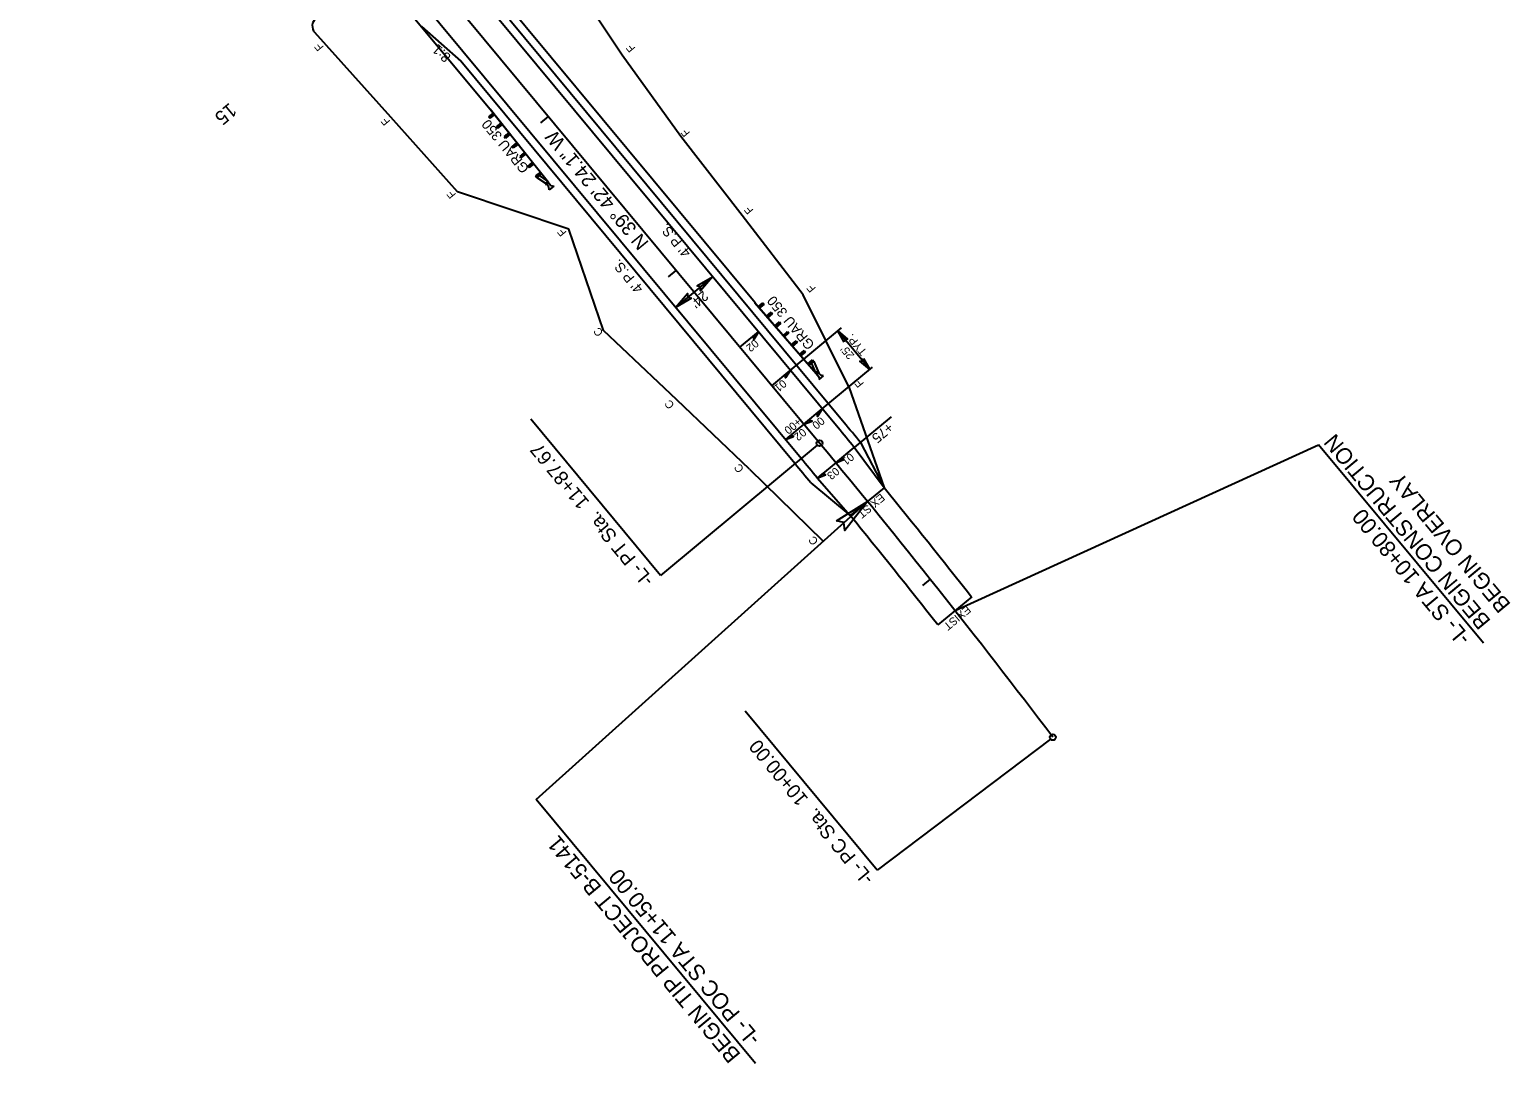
# Model space of a CAD drawing. Extents: x 2597570 to 2598622, y 852675 to 853890.
# Drawn here: x 2597882 to 2598622, y 852675 to 853192 of the extents above; entities that cross this region are included whole.
import ezdxf

# ---------------------------------------------------------------- set-up
doc = ezdxf.new("R2010")
doc.units = 0
for name, color, linetype in [('Exist Drainage Structure Bridge Pier Bent Interior', 7, 'Continuous'), ('Exist Hydrographic Channel Edge', 7, 'Continuous'), ('Exist Plan Preparation Drainage Arrows Symbol CELL', 7, 'Continuous'), ('Exist Plan Preparation Watershed Blue', 7, 'Continuous'), ('Exist Structure Major Deck Tunnel Box Culvert', 7, 'Continuous'), ('Prop Drainage Structure Box Number Symbol CELL', 7, 'Continuous'), ('Prop Drainage Structure Drop Inlet Grate 2 Narrow Slots and Flat Grates 840 29 Label', 7, 'Continuous'), ('Prop Drainage Structure Gutter Shoulder Berm Label', 7, 'Continuous'), ('Prop Drainage Structure Pipe Alternate 15in', 7, 'Continuous'), ('Prop Drainage Structure Pipe Alternate 15in Label', 7, 'Continuous'), ('Prop Drainage Structure Pipe RCP 15in Class IV', 7, 'Continuous'), ('Prop Drainage Structure Pipe RCP 15in Class IV Label', 7, 'Continuous'), ('Prop Drainage Structure Plot Symbol 20 Scale', 7, 'Continuous'), ('Prop Drainage Structure Plot Symbol 50 Scale', 7, 'Continuous'), ('Prop Earthen Structure Base Ditch Berm Detail Label', 7, 'Continuous'), ('Prop Earthen Structure Ditch Flow Line', 7, 'Continuous'), ('Prop Erosion Rip Rap Pad at Outlet CELL', 7, 'Continuous'), ('Prop Erosion Rip Rap Pad at Outlet Label', 7, 'Continuous'), ('Raster_Level_0', 7, 'Continuous'), ('Typical Terminator CELL', 7, 'Continuous')]:
    doc.layers.add(name, color=color, linetype=linetype)

msp = doc.modelspace()

# ---------------------------------------------------------------- linework, layer by layer
at = {"layer": 'Exist Drainage Structure Bridge Pier Bent Interior'}
for p, q in [((2598196.95, 852918.86), (2598132.12, 852996.93)), ((2598275.35, 852983.97), (2598196.95, 852918.86)), ((2598305.3, 852771.42), (2598239.24, 852850.98)), ((2598391.92, 852837), (2598305.3, 852771.42))]:
    msp.add_line(p, q, dxfattribs=at)
for centre in [(2598276.51, 852984.93), (2598393.11, 852837.9)]:
    msp.add_circle(centre, 1.5, dxfattribs=at)
at = {"layer": 'Exist Hydrographic Channel Edge'}
msp.add_line((2598276.51, 852984.93), (2597890.84, 853449.35), dxfattribs=at)
msp.add_line((2598276.51, 852984.93), (2597890.84, 853449.35), dxfattribs=at)
msp.add_arc((2595067.53, 850320.15), 4171.16, 37.12886, 39.70669, dxfattribs=at)
msp.add_arc((2595067.53, 850320.15), 4171.16, 37.12886, 39.70669, dxfattribs=at)
at = {"layer": 'Exist Plan Preparation Drainage Arrows Symbol CELL'}
for p, q in [((2598140.86, 853148.28), (2598137.01, 853145.09)), ((2598204.74, 853071.35), (2598200.9, 853068.16)), ((2598268.63, 852994.42), (2598264.78, 852991.22)), ((2598331.8, 852916.9), (2598327.89, 852913.79))]:
    msp.add_line(p, q, dxfattribs=at)
at = {"layer": 'Exist Plan Preparation Watershed Blue'}
for p, q in [((2598113.37, 853150), (2598111.02, 853148.13)), ((2598112.82, 853148.28), (2598111.02, 853148.13)), ((2598111.02, 853148.13), (2598111.65, 853147.35)), ((2598113.99, 853149.22), (2598111.65, 853147.35)), ((2598111.65, 853147.35), (2598112.2, 853149.06)), ((2598111.78, 853151.99), (2598140.93, 853115.43)), ((2598112.2, 853149.06), (2598113.99, 853149.22)), ((2598112.2, 853149.06), (2598112.82, 853148.28)), ((2598112.82, 853148.28), (2598113.37, 853150)), ((2598113.99, 853149.22), (2598112.82, 853148.28)), ((2598113.37, 853150), (2598113.99, 853149.22)), ((2598117.3, 853145.07), (2598114.91, 853143.17)), ((2598116.73, 853143.34), (2598114.91, 853143.17)), ((2598114.91, 853143.17), (2598115.53, 853142.39)), ((2598117.92, 853144.29), (2598115.53, 853142.39)), ((2598115.53, 853142.39), (2598116.1, 853144.12)), ((2598116.1, 853144.12), (2598117.92, 853144.29)), ((2598116.1, 853144.12), (2598116.73, 853143.34)), ((2598117.3, 853145.07), (2598116.73, 853143.34)), ((2598121.23, 853140.15), (2598118.84, 853138.25)), ((2598121.85, 853139.36), (2598119.47, 853137.46)), ((2598119.47, 853137.46), (2598120.03, 853139.2)), ((2598120.03, 853139.2), (2598121.85, 853139.36)), ((2598120.03, 853139.2), (2598120.66, 853138.41)), ((2598121.23, 853140.15), (2598120.66, 853138.41)), ((2598120.66, 853138.41), (2598118.84, 853138.25)), ((2598118.84, 853138.25), (2598119.47, 853137.46)), ((2598125.15, 853135.22), (2598122.78, 853133.33)), ((2598124.59, 853133.49), (2598122.78, 853133.33)), ((2598122.78, 853133.33), (2598123.4, 853132.54)), ((2598125.78, 853134.44), (2598123.4, 853132.54)), ((2598123.4, 853132.54), (2598123.97, 853134.27)), ((2598123.97, 853134.27), (2598125.78, 853134.44)), ((2598123.97, 853134.27), (2598124.59, 853133.49)), ((2598125.15, 853135.22), (2598124.59, 853133.49)), ((2598125.15, 853135.22), (2598125.78, 853134.44)), ((2598129.08, 853130.29), (2598126.63, 853128.34)), ((2598128.48, 853128.53), (2598126.63, 853128.34)), ((2598126.63, 853128.34), (2598127.25, 853127.55)), ((2598129.71, 853129.51), (2598127.25, 853127.55)), ((2598127.25, 853127.55), (2598127.86, 853129.32)), ((2598127.86, 853129.32), (2598129.71, 853129.51)), ((2598127.86, 853129.32), (2598128.48, 853128.53)), ((2598129.08, 853130.29), (2598128.48, 853128.53)), ((2598133.01, 853125.37), (2598130.67, 853123.5)), ((2598133.63, 853124.58), (2598131.29, 853122.71)), ((2598131.29, 853122.71), (2598131.84, 853124.43)), ((2598131.84, 853124.43), (2598133.63, 853124.58)), ((2598131.84, 853124.43), (2598132.46, 853123.65)), ((2598133.01, 853125.37), (2598132.46, 853123.65)), ((2598132.46, 853123.65), (2598130.67, 853123.5)), ((2598130.67, 853123.5), (2598131.29, 853122.71)), ((2598136.94, 853120.44), (2598134.54, 853118.53)), ((2598136.37, 853118.7), (2598134.54, 853118.53)), ((2598134.54, 853118.53), (2598135.17, 853117.75)), ((2598137.56, 853119.66), (2598135.17, 853117.75)), ((2598135.17, 853117.75), (2598135.74, 853119.48)), ((2598135.17, 853117.75), (2598139.45, 853114.89)), ((2598135.74, 853119.48), (2598137.56, 853119.66)), ((2598135.74, 853119.48), (2598136.37, 853118.7)), ((2598136.94, 853120.44), (2598136.37, 853118.7)), ((2598136.37, 853118.7), (2598140.62, 853115.82)), ((2598140.62, 853115.82), (2598139.45, 853114.89)), ((2598141.24, 853115.04), (2598139.45, 853114.89)), ((2598139.45, 853114.89), (2598139.76, 853114.5)), ((2598139.45, 853114.89), (2598140.07, 853114.11)), ((2598139.95, 853114.58), (2598140.42, 853114.97)), ((2598141.25, 853113.01), (2598139.95, 853114.58)), ((2598140.07, 853114.11), (2598140.62, 853115.82)), ((2598141.24, 853115.04), (2598140.07, 853114.11)), ((2598140.42, 853114.97), (2598140.89, 853115.36)), ((2598140.89, 853115.36), (2598142.2, 853113.78)), ((2598141.35, 853111.55), (2598141.25, 853113.01)), ((2598143.61, 853113.43), (2598141.35, 853111.55)), ((2598142.2, 853113.78), (2598143.61, 853113.43)), ((2598244.23, 853055.06), (2598274.81, 853019.7)), ((2598245.89, 853053.14), (2598248.16, 853055.1)), ((2598247.68, 853053.37), (2598245.89, 853053.14)), ((2598245.89, 853053.14), (2598246.55, 853052.39)), ((2598246.55, 853052.39), (2598248.82, 853054.35)), ((2598247.03, 853054.12), (2598246.55, 853052.39)), ((2598246.55, 853052.39), (2598247.68, 853053.37)), ((2598248.82, 853054.35), (2598247.03, 853054.12)), ((2598247.03, 853054.12), (2598247.68, 853053.37)), ((2598247.68, 853053.37), (2598248.16, 853055.1)), ((2598248.16, 853055.1), (2598248.82, 853054.35)), ((2598250.01, 853048.38), (2598252.32, 853050.37)), ((2598251.82, 853048.62), (2598252.32, 853050.37)), ((2598252.32, 853050.37), (2598252.98, 853049.62)), ((2598250.01, 853048.38), (2598251.82, 853048.62)), ((2598250.67, 853047.62), (2598252.98, 853049.62)), ((2598251.17, 853049.37), (2598250.67, 853047.62)), ((2598252.98, 853049.62), (2598251.17, 853049.37)), ((2598251.17, 853049.37), (2598251.82, 853048.62)), ((2598254.13, 853043.61), (2598256.44, 853045.6)), ((2598254.13, 853043.61), (2598255.94, 853043.85)), ((2598254.79, 853042.85), (2598257.09, 853044.85)), ((2598255.29, 853044.61), (2598254.79, 853042.85)), ((2598257.09, 853044.85), (2598255.29, 853044.61)), ((2598255.29, 853044.61), (2598255.94, 853043.85)), ((2598255.94, 853043.85), (2598256.44, 853045.6)), ((2598256.44, 853045.6), (2598257.09, 853044.85)), ((2598258.26, 853038.84), (2598260.55, 853040.83)), ((2598258.26, 853038.84), (2598260.06, 853039.08)), ((2598258.26, 853038.84), (2598258.91, 853038.09)), ((2598258.91, 853038.09), (2598261.21, 853040.07)), ((2598259.41, 853039.84), (2598258.91, 853038.09)), ((2598261.21, 853040.07), (2598259.41, 853039.84)), ((2598259.41, 853039.84), (2598260.06, 853039.08)), ((2598260.06, 853039.08), (2598260.55, 853040.83)), ((2598260.55, 853040.83), (2598261.21, 853040.07)), ((2598262.38, 853034.08), (2598264.75, 853036.13)), ((2598263.03, 853033.32), (2598265.41, 853035.37)), ((2598265.41, 853035.37), (2598263.56, 853035.1)), ((2598264.22, 853034.35), (2598264.75, 853036.13)), ((2598264.75, 853036.13), (2598265.41, 853035.37)), ((2598262.38, 853034.08), (2598264.22, 853034.35)), ((2598263.56, 853035.1), (2598263.03, 853033.32)), ((2598263.56, 853035.1), (2598264.22, 853034.35)), ((2598266.5, 853029.31), (2598268.77, 853031.27)), ((2598266.5, 853029.31), (2598268.29, 853029.53)), ((2598267.15, 853028.55), (2598269.42, 853030.51)), ((2598267.63, 853030.29), (2598267.15, 853028.55)), ((2598269.42, 853030.51), (2598267.63, 853030.29)), ((2598267.63, 853030.29), (2598268.29, 853029.53)), ((2598268.29, 853029.53), (2598268.77, 853031.27)), ((2598268.77, 853031.27), (2598269.42, 853030.51)), ((2598270.62, 853024.54), (2598272.94, 853026.55)), ((2598270.62, 853024.54), (2598272.43, 853024.79)), ((2598271.28, 853023.79), (2598273.59, 853025.79)), ((2598271.78, 853025.54), (2598271.28, 853023.79)), ((2598273.59, 853025.79), (2598271.78, 853025.54)), ((2598271.78, 853025.54), (2598272.43, 853024.79)), ((2598272.43, 853024.79), (2598272.94, 853026.55)), ((2598272.43, 853024.79), (2598274.48, 853020.08)), ((2598272.94, 853026.55), (2598273.59, 853025.79)), ((2598273.59, 853025.79), (2598275.62, 853021.06)), ((2598274.48, 853020.08), (2598275.62, 853021.06)), ((2598275.13, 853019.32), (2598275.62, 853021.06)), ((2598275.62, 853021.06), (2598275.94, 853020.68)), ((2598275.62, 853021.06), (2598276.27, 853020.3)), ((2598276.27, 853020.3), (2598274.48, 853020.08)), ((2598275.35, 853020.12), (2598274.89, 853019.73)), ((2598274.89, 853019.73), (2598276.2, 853018.15)), ((2598275.13, 853019.32), (2598276.27, 853020.3)), ((2598275.82, 853020.51), (2598275.35, 853020.12)), ((2598277.13, 853018.94), (2598275.82, 853020.51)), ((2598276.2, 853018.15), (2598276.29, 853016.7)), ((2598276.29, 853016.7), (2598278.55, 853018.58)), ((2598278.55, 853018.58), (2598277.13, 853018.94))]:
    msp.add_line(p, q, dxfattribs=at)
at = {"layer": 'Prop Drainage Structure Box Number Symbol CELL'}
for points in [[(2598215.08, 853063.59), (2598222.99, 853068.15), (2598217.05, 853061.14), (2598216.92, 853063.1)], [(2598212.44, 853057.37), (2598204.53, 853052.82), (2598210.47, 853059.83), (2598210.61, 853057.86)], [(2598288.82, 853035.49), (2598285.63, 853041.03), (2598290.54, 853036.87), (2598289.16, 853036.78)], [(2598298.41, 853027.34), (2598301.6, 853021.8), (2598296.69, 853025.96), (2598298.07, 853026.05)], [(2598284.99, 852946.1), (2598300.44, 852955.84), (2598289.13, 852941.35), (2598288.7, 852945.27)]]:
    msp.add_lwpolyline(points, close=True, dxfattribs=at)
at = {"layer": 'Prop Drainage Structure Drop Inlet Grate 2 Narrow Slots and Flat Grates 840 29 Label'}
for points in [[(2598245.92, 853040.55), (2598243.58, 853036.79), (2598243.42, 853038.48)], [(2598261.89, 853021.32), (2598259.55, 853017.56), (2598259.4, 853019.25)], [(2598277.86, 853002.08), (2598275.52, 852998.33), (2598275.37, 853000.02)], [(2598268.63, 852994.42), (2598272.75, 852996.03), (2598271.12, 852996.49)], [(2598259.4, 852986.75), (2598263.52, 852988.36), (2598261.89, 852988.82)], [(2598284.6, 852975.18), (2598288.72, 852976.79), (2598287.09, 852977.26)], [(2598275.35, 852967.51), (2598279.48, 852969.12), (2598277.84, 852969.58)]]:
    msp.add_lwpolyline(points, close=True, dxfattribs=at)
at = {"layer": 'Prop Drainage Structure Gutter Shoulder Berm Label'}
for p, q in [((2598223, 853068.15), (2598204.53, 853052.82)), ((2598312.3, 852998.18), (2598293.83, 852982.85))]:
    msp.add_line(p, q, dxfattribs=at)
at = {"layer": 'Prop Drainage Structure Pipe Alternate 15in'}
for p, q in [((2598168.51, 853041.26), (2598151.17, 853091.85)), ((2598291.22, 853013.18), (2598308.74, 852962.61)), ((2598241.49, 852971.88), (2598278.09, 852936.11))]:
    msp.add_line(p, q, dxfattribs=at)
at = {"layer": 'Prop Drainage Structure Pipe RCP 15in Class IV'}
for p, q in [((2598177.77, 853178.93), (2598150.05, 853220.91)), ((2598062.12, 853147.89), (2598024.19, 853190.17)), ((2598207.09, 853138.29), (2598177.77, 853178.93)), ((2598095.49, 853110.61), (2598062.12, 853147.89)), ((2598237.81, 853098.81), (2598207.09, 853138.29)), ((2598151.17, 853091.85), (2598095.49, 853110.61)), ((2598268.26, 853059.11), (2598237.81, 853098.81)), ((2598291.22, 853013.18), (2598268.26, 853059.11)), ((2598291.22, 853013.18), (2598291.22, 853013.18))]:
    msp.add_line(p, q, dxfattribs=at)
msp.add_arc((2598027.92, 853193.51), 5, 129.70669, 221.8952, dxfattribs=at)
at = {"layer": 'Prop Drainage Structure Pipe RCP 15in Class IV Label'}
for p, q in [((2598344.22, 852901.22), (2598525.93, 852984.16)), ((2598608.35, 852884.9), (2598525.93, 852984.16)), ((2598134.88, 852806.8), (2598300.44, 852955.84)), ((2598244.4, 852674.91), (2598134.88, 852806.8))]:
    msp.add_line(p, q, dxfattribs=at)
at = {"layer": 'Prop Drainage Structure Plot Symbol 20 Scale'}
for p, q in [((2598285.74, 852992.6), (2597900.08, 853457.02)), ((2598267.28, 852977.26), (2597881.61, 853441.69)), ((2598308.74, 852962.61), (2598293.82, 852982.84)), ((2598275.28, 852967.59), (2598291.8, 852948.8)), ((2598352.67, 852908.11), (2598335.58, 852894.18))]:
    msp.add_line(p, q, dxfattribs=at)
for centre, radius, start, end in [((2595076.76, 850327.82), 4171.16, 39.53269, 39.70669), ((2595067.53, 850320.15), 4159.16, 39.53368, 39.70669), ((2595067.53, 850320.15), 4181.87, 38.23022, 39.18929), ((2595067.53, 850320.15), 4160.01, 38.22518, 39.18929)]:
    msp.add_arc(centre, radius, start, end, dxfattribs=at)
at = {"layer": 'Prop Drainage Structure Plot Symbol 50 Scale'}
for p, q in [((2598077.56, 853193.2), (2598097.17, 853175.85)), ((2598288.82, 852995.15), (2598121.7, 853196.4)), ((2598264.2, 852974.71), (2598097.17, 853175.85)), ((2598296.97, 852985.3), (2598308.74, 852962.61)), ((2598272.2, 852965.04), (2598291.8, 852948.8)), ((2598291.8, 852948.8), (2598291.8, 852948.8))]:
    msp.add_line(p, q, dxfattribs=at)
for radius, start in [(4187.16, 39.53171), (4155.16, 39.53368)]:
    msp.add_arc((2595067.53, 850320.15), radius, start, 39.70669, dxfattribs=at)
at = {"layer": 'Prop Earthen Structure Ditch Flow Line'}
for p, q in [((2598236.69, 853032.88), (2598245.92, 853040.55)), ((2598261.89, 853021.32), (2598287.43, 853042.53)), ((2598301.6, 853021.8), (2598285.63, 853041.03)), ((2598252.66, 853013.65), (2598261.89, 853021.32)), ((2598277.86, 853002.08), (2598302.92, 853022.9)), ((2598268.63, 852994.42), (2598277.86, 853002.08)), ((2598268.63, 852994.42), (2598259.4, 852986.75)), ((2598284.6, 852975.18), (2598293.83, 852982.85)), ((2598284.59, 852975.17), (2598275.35, 852967.51)), ((2598308.74, 852962.61), (2598291.8, 852948.8))]:
    msp.add_line(p, q, dxfattribs=at)
at = {"layer": 'Prop Erosion Rip Rap Pad at Outlet CELL'}
for p, q in [((2598244.24, 853055.07), (2598096.7, 853232.76)), ((2598065.93, 853207.21), (2598111.78, 853151.99)), ((2598133.05, 853125.27), (2598111.78, 853151.99)), ((2598276.2, 853018.15), (2598244.23, 853055.06))]:
    msp.add_line(p, q, dxfattribs=at)
at = {"layer": 'Typical Terminator CELL'}
for p, q in [((2598205.08, 853006.64), (2598168.51, 853041.26)), ((2598241.49, 852971.88), (2598205.08, 853006.64))]:
    msp.add_line(p, q, dxfattribs=at)

# ---------------------------------------------------------------- texts
at = {"layer": 'Exist Drainage Structure Bridge Pier Bent Interior'}
for s, rotation, p in [('-L- PT Sta.  11+87.67', 129.70669, (2598194.04, 852916.72)), ('-L- PC Sta.  10+00.00', 129.66534, (2598304.03, 852767.58))]:
    msp.add_text(s, height=7, rotation=rotation, dxfattribs=at).set_placement(p)
at = {"layer": 'Exist Plan Preparation Watershed Blue'}
for p in [(2598131.67, 853122.45), (2598274.34, 853034.22)]:
    msp.add_text('GRAU 350', height=5, rotation=129.70669, dxfattribs=at).set_placement(p)
at = {"layer": 'Exist Structure Major Deck Tunnel Box Culvert'}
msp.add_text('N 39%%d 42\' 24.1" W', height=7, rotation=129.70669, dxfattribs=at).set_placement((2598191.47, 853085.21))
at = {"layer": 'Prop Drainage Structure Pipe Alternate 15in Label'}
for s, p in [('BEGIN CONSTRUCTION', (2598612.41, 852896.09)), ('BEGIN OVERLAY', (2598622.41, 852904.39)), ('-L- STA 10+80.00', (2598602.41, 852887.78)), ('BEGIN TIP PROJECT B-5141', (2598237.45, 852679.33)), ('-L- POC STA 11+50.00', (2598247.45, 852687.64))]:
    msp.add_text(s, height=8, rotation=129.70669, dxfattribs=at).set_placement(p)
at = {"layer": 'Prop Earthen Structure Base Ditch Berm Detail Label'}
for s, p in [('F', (2598028.87, 853183.02)), ('F', (2598184.66, 853182.41)), ('F', (2598062.08, 853145.81)), ('F', (2598212.01, 853140.12)), ('F', (2598095, 853109.29)), ('F', (2598243.69, 853101.44)), ('F', (2598150.29, 853090.37)), ('F', (2598274.92, 853062.38)), ('C', (2598168.66, 853040.3)), ('F', (2598298.91, 853014.79)), ('C', (2598204.2, 853004.06)), ('C', (2598238.95, 852972.17)), ('C', (2598276.15, 852935.97))]:
    msp.add_text(s, height=4, rotation=129.70669, dxfattribs=at).set_placement(p)
at = {"layer": 'Prop Earthen Structure Ditch Flow Line'}
for s, rotation, p in [('02', 219.70669, (2598244.01, 853037.12)), ('TYP.', 129.70669, (2598300.43, 853030.82)), ("25'", 130.70669, (2598294.14, 853028.96)), ('01', 219.70669, (2598257.96, 853017.04)), ('+00', 219.70669, (2598265.42, 852997.91)), ('02', 219.70669, (2598267.86, 852992.64)), ('00', 219.70669, (2598276.99, 852998.42)), ('01', 219.70669, (2598291.73, 852980.36)), ('03', 219.70669, (2598284.42, 852973.21)), ('EXIST', 219.70669, (2598307.06, 852960.05)), ('EXIST', 219.70669, (2598350.07, 852904.05))]:
    msp.add_text(s, height=4, rotation=rotation, dxfattribs=at).set_placement(p)
at = {"layer": 'Prop Erosion Rip Rap Pad at Outlet Label'}
for s, rotation, p in [('8:1', 138.49397, (2598092.61, 853178.55)), ("4' P.S.", 129.70669, (2598212.5, 853080.35)), ("4' P.S.", 129.70669, (2598188.7, 853062.42)), ("24'", 219.70669, (2598218.33, 853061.45)), ('+75', 219.70669, (2598310.87, 852995.64))]:
    msp.add_text(s, height=5, rotation=rotation, dxfattribs=at).set_placement(p)
at = {"layer": 'Raster_Level_0'}
msp.add_text('15', height=7, rotation=219.70669, dxfattribs=at).set_placement((2597981.53, 853155.45))

doc.saveas('drawing.dxf')
